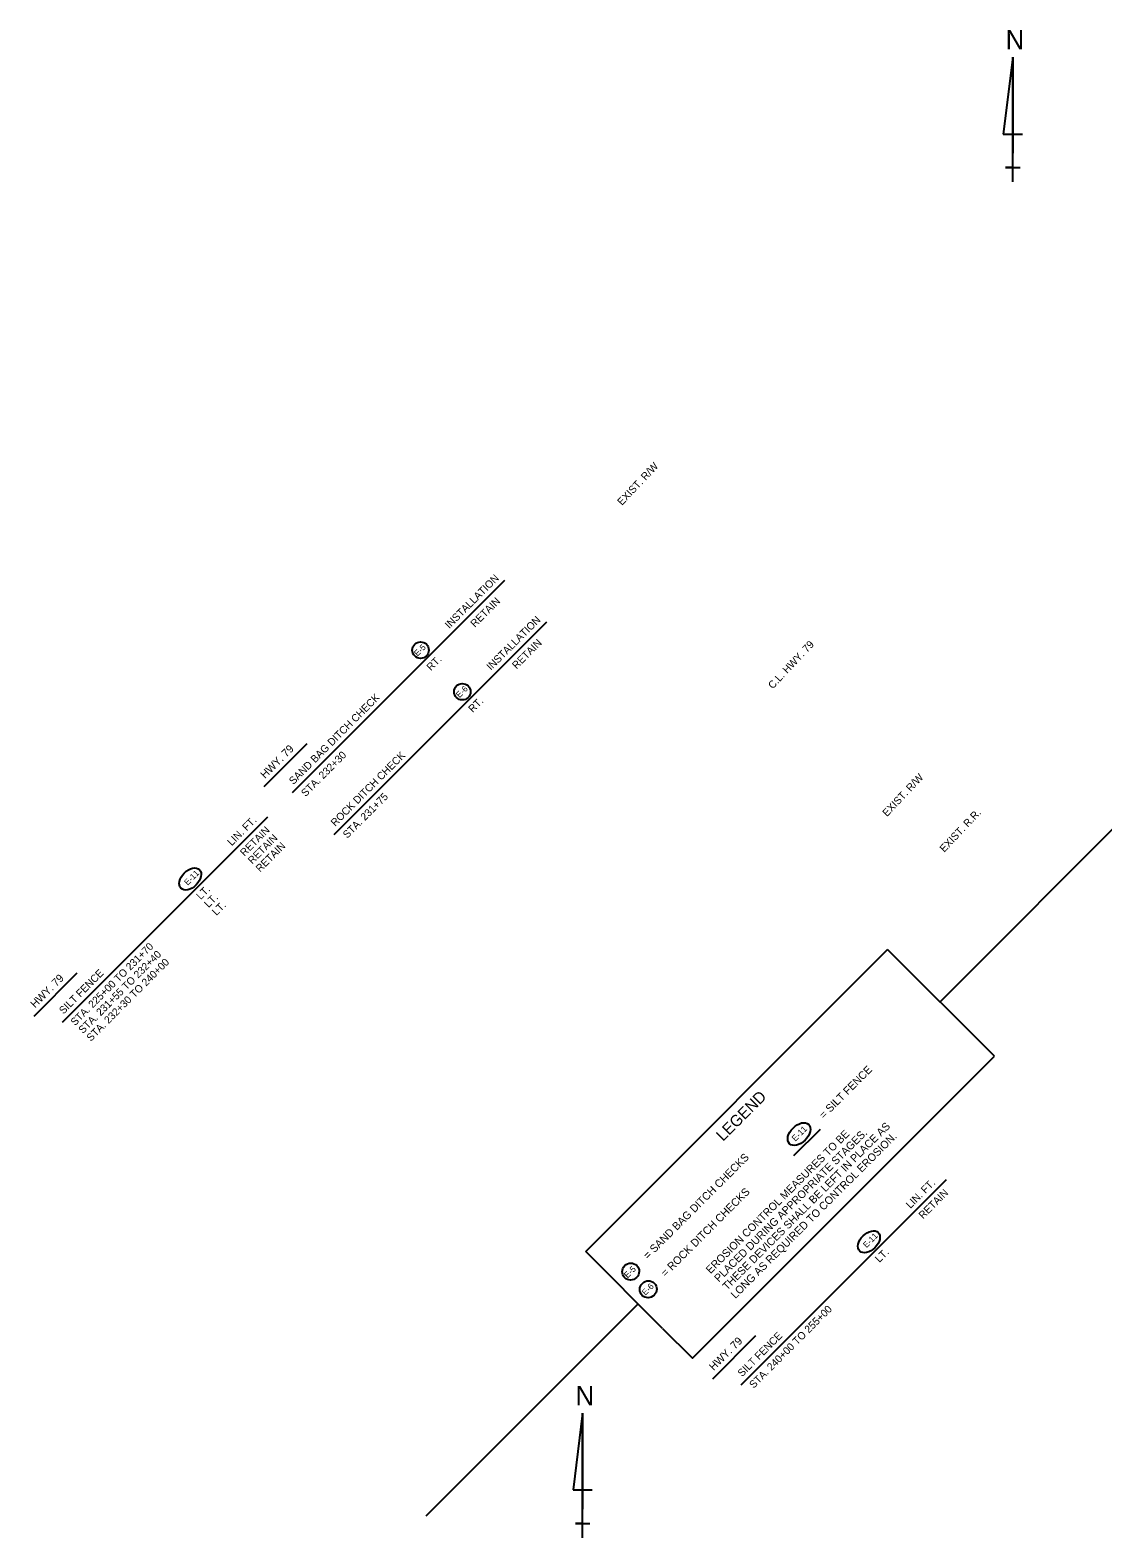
# Model space of a CAD drawing. Extents: x 1388120 to 1389841, y 1944307 to 1945760.
# Drawn here: x 1388120 to 1388980, y 1944307 to 1945516 of the extents above; entities that cross this region are included whole.
import ezdxf

# ---------------------------------------------------------------- set-up
doc = ezdxf.new("R2010")
doc.units = 0
for name, color, linetype in [('1', 7, 'Continuous'), ('44', 7, 'Continuous'), ('63', 7, 'Continuous'), ('Level 1', 7, 'Continuous'), ('Level 44', 7, 'Continuous'), ('R_Draft', 7, 'Continuous')]:
    doc.layers.add(name, color=color, linetype=linetype)

msp = doc.modelspace()

# ---------------------------------------------------------------- linework, layer by layer
at = {"layer": '1'}
for p, q in [((1388849.6, 1944736.7), (1389051.9, 1944939.1)), ((1388565.3, 1944536.4), (1388807.6, 1944778.6)), ((1388893.2, 1944693.1), (1388807.6, 1944778.6)), ((1388627, 1944474.7), (1388565.3, 1944536.4)), ((1388437.2, 1944324.3), (1388607.3, 1944494.4))]:
    msp.add_line(p, q, dxfattribs=at)
msp.add_lwpolyline([(1388627, 1944474.7), (1388650.9, 1944450.8), (1388893.2, 1944693.1)], dxfattribs=at)
for centre in [(1388432.8, 1945018.8), (1388466.3, 1944985.4)]:
    msp.add_circle(centre, 6.61, dxfattribs=at)
for centre in [(1388248, 1944835.2), (1388792.6, 1944544.2)]:
    msp.add_ellipse(centre, major_axis=(7.44, 7.44), ratio=0.638788, dxfattribs=at)
at = {"layer": '44'}
for p, q in [((1388330.1, 1944904.5), (1388500.5, 1945074.9)), ((1388363.6, 1944871), (1388534, 1945041.4)), ((1388307.3, 1944909.3), (1388341.8, 1944943.9)), ((1388145.6, 1944720.4), (1388310.2, 1944885)), ((1388122.7, 1944725.3), (1388157.3, 1944759.8)), ((1388690.1, 1944429.5), (1388854.7, 1944594.1)), ((1388667.3, 1944434.3), (1388701.8, 1944468.9))]:
    msp.add_line(p, q, dxfattribs=at)
at = {"layer": '63'}
for p, q in [((1388908, 1945494.3), (1388900.3, 1945432.7)), ((1388908, 1945394.3), (1388908, 1945494.3)), ((1388908, 1945494.3), (1388908, 1945417.4)), ((1388900.3, 1945432.7), (1388915.7, 1945432.7)), ((1388908, 1945394.3), (1388908, 1945417.4)), ((1388908, 1945405.8), (1388902.2, 1945405.8)), ((1388902.2, 1945405.8), (1388913.8, 1945405.8)), ((1388908, 1945394.3), (1388908, 1945405.8)), ((1388562.8, 1944406.7), (1388555.2, 1944345.2)), ((1388562.8, 1944306.7), (1388562.8, 1944406.7)), ((1388562.8, 1944406.7), (1388562.8, 1944329.8)), ((1388555.2, 1944345.2), (1388570.5, 1944345.2)), ((1388562.8, 1944306.7), (1388562.8, 1944329.8)), ((1388562.8, 1944318.3), (1388557.1, 1944318.3)), ((1388557.1, 1944318.3), (1388568.6, 1944318.3)), ((1388562.8, 1944306.7), (1388562.8, 1944318.3))]:
    msp.add_line(p, q, dxfattribs=at)
at = {"layer": 'Level 1'}
for centre, major_axis, ratio in [((1388736.5, 1944630.6), (7.75, 7.75), 0.622952), ((1388601.4, 1944520.3), (-4.87, -4.86), 0.97521), ((1388615.5, 1944506.1), (-4.87, -4.86), 0.97521)]:
    msp.add_ellipse(centre, major_axis=major_axis, ratio=ratio, dxfattribs=at)
at = {"layer": 'Level 44'}
msp.add_lwpolyline([(1388732.4, 1944613.3), (1388753.7, 1944634.6)], dxfattribs=at)

# ---------------------------------------------------------------- texts
at = {"layer": '1'}
for s, p in [('E-5 ', (1388430.4, 1945013.5)), ('E-6 ', (1388464.1, 1944980.2)), ('E-11', (1388246, 1944829.8)), ('E-11', (1388790.6, 1944538.9))]:
    msp.add_text(s, height=4.8, rotation=45, dxfattribs=at).set_placement(p)
at = {"layer": '44'}
for s, height, p in [('INSTALLATION', 6, (1388455.9, 1945035.6)), ('RETAIN', 6, (1388476.4, 1945036.7)), ('INSTALLATION', 6, (1388489.3, 1945002.1)), ('RETAIN', 6, (1388509.8, 1945003.2)), ('RT.', 6, (1388441.2, 1945001.8)), ('SAND BAG DITCH CHECK', 6, (1388330.8, 1944910.5)), ('RT.', 6, (1388474.7, 1944968.3)), ('HWY. 79', 6.25, (1388308, 1944915.4)), ('STA. 232+30', 6, (1388340.5, 1944900.8)), ('ROCK DITCH CHECK', 6, (1388364.3, 1944877)), ('STA. 231+75', 6, (1388374, 1944867.4)), ('LIN. FT.', 6, (1388281.3, 1944861.4)), ('RETAIN', 6, (1388291.5, 1944853)), ('RETAIN', 6, (1388297.8, 1944846.7)), ('RETAIN', 6, (1388304.1, 1944840.3)), ('LT.', 6, (1388256.4, 1944818.2)), ('LT.', 6, (1388262.7, 1944811.8)), ('LT.', 6, (1388269.1, 1944805.5)), ('STA. 225+00 TO 231+70', 6, (1388155.6, 1944717.1)), ('STA. 231+55 TO 232+40', 6, (1388161.9, 1944710.8)), ('STA. 232+30 TO 240+00', 6, (1388168.3, 1944704.5)), ('HWY. 79', 6.25, (1388123.5, 1944731.4)), ('SILT FENCE      ', 6, (1388146.3, 1944726.4)), ('LIN. FT.', 6, (1388825.8, 1944570.5)), ('RETAIN', 6, (1388836, 1944562.1)), ('LT.', 6, (1388801, 1944527.2)), ('STA. 240+00 TO 255+00', 6, (1388700.1, 1944426.2)), ('HWY. 79', 6.25, (1388668, 1944440.4)), ('SILT FENCE      ', 6, (1388690.8, 1944435.5))]:
    msp.add_text(s, height=height, rotation=45, dxfattribs=at).set_placement(p)
at = {"layer": '63'}
for p in [(1388902.3, 1945500.7), (1388557.2, 1944413.1)]:
    msp.add_text('N', height=15.4, rotation=360, dxfattribs=at).set_placement(p)
at = {"layer": 'Level 1'}
for s, height, p in [('= SILT FENCE', 6.25, (1388756.4, 1944642.4)), ('THESE DEVICES SHALL BE LEFT IN PLACE AS ', 6.25, (1388678.8, 1944504.9)), ('E-11 ', 4.88, (1388733.6, 1944624.4)), ('EROSION CONTROL MEASURES TO BE', 6.25, (1388665.5, 1944518.2)), ('PLACED DURING APPROPRIATE STAGES. ', 6.25, (1388672.2, 1944511.5)), ('LONG AS REQUIRED TO CONTROL EROSION.', 6.25, (1388685.5, 1944498.2)), ('= SAND BAG DITCH CHECKS', 6.25, (1388615.3, 1944529.8)), ('= ROCK DITCH CHECKS', 6.25, (1388629.4, 1944515.6)), ('E-5 ', 4.88, (1388598.9, 1944514.7)), ('E-6 ', 4.88, (1388613.2, 1944500.8))]:
    msp.add_text(s, height=height, rotation=45, dxfattribs=at).set_placement(p)
at = {"layer": 'Level 44'}
msp.add_text('LEGEND', height=9.14, rotation=45, dxfattribs=at).set_placement((1388675.5, 1944624.3))
at = {"layer": 'R_Draft'}
for s, rotation, p in [('EXIST. R/W', 46.6607, (1388594.4, 1945134.4)), ('C.L. HWY. 79', 46.736, (1388715.4, 1944987.2)), ('EXIST. R/W', 46.6607, (1388807.1, 1944884.8)), ('EXIST. R.R.', 46.6607, (1388853, 1944856.2))]:
    msp.add_text(s, height=6, rotation=rotation, dxfattribs=at).set_placement(p)

doc.saveas('drawing.dxf')
